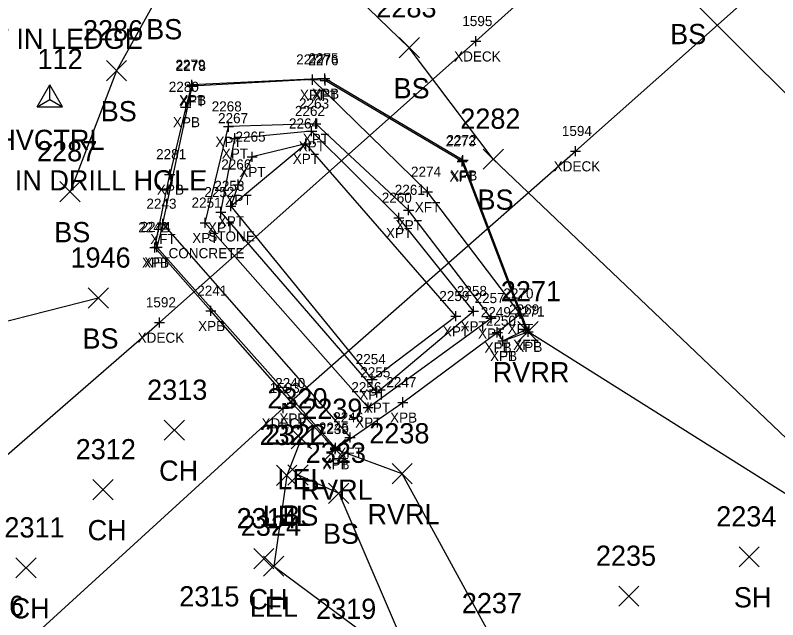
# Model space of a CAD drawing. Extents: x 1647133 to 1649138, y 411736 to 414924.
# Drawn here: x 1648877.6 to 1648953, y 412120.2 to 412180 of the extents above; entities that cross this region are included whole.
import ezdxf

# ---------------------------------------------------------------- set-up
doc = ezdxf.new("R2010")
doc.units = 0
for name, color, linetype in [('B_A', 7, 'Continuous'), ('B_C', 7, 'Continuous'), ('B_I', 7, 'Continuous'), ('B_TIC', 7, 'Continuous'), ('BELB', 7, 'Continuous'), ('BFT', 7, 'Continuous'), ('BSUBM', 7, 'Continuous'), ('C_A', 7, 'Continuous'), ('C_C', 7, 'Continuous'), ('C_I', 7, 'Continuous'), ('CPSM', 7, 'Continuous'), ('L_A', 7, 'Continuous'), ('L_I', 7, 'Continuous'), ('L_TIC', 7, 'Continuous'), ('LARO', 7, 'Continuous'), ('LAWE', 7, 'Continuous'), ('LELB', 7, 'Continuous')]:
    doc.layers.add(name, color=color, linetype=linetype)

msp = doc.modelspace()

# ---------------------------------------------------------------- linework, layer by layer
at = {"layer": 'B_TIC'}
for p, q in [((1648923.128, 412177.419), (1648923.203, 412177.419)), ((1648906.986, 412173.626), (1648907.061, 412173.626)), ((1648906.986, 412173.626), (1648907.061, 412173.626)), ((1648908.195, 412173.736), (1648908.27, 412173.736)), ((1648908.226, 412173.547), (1648908.302, 412173.547)), ((1648895.051, 412173.099), (1648895.126, 412173.099)), ((1648895.086, 412172.978), (1648895.162, 412172.978)), ((1648895.086, 412172.978), (1648895.162, 412172.978)), ((1648894.438, 412170.92), (1648894.513, 412170.92)), ((1648898.657, 412168.981), (1648898.733, 412168.981)), ((1648898.657, 412168.981), (1648898.733, 412168.981)), ((1648907.293, 412169.271), (1648907.368, 412169.271)), ((1648906.884, 412168.533), (1648906.96, 412168.533)), ((1648899.286, 412167.819), (1648899.362, 412167.819)), ((1648899.286, 412167.819), (1648899.362, 412167.819)), ((1648906.3, 412167.296), (1648906.376, 412167.296)), ((1648906.3, 412167.296), (1648906.376, 412167.296)), ((1648932.968, 412166.557), (1648933.043, 412166.557)), ((1648901.013, 412165.993), (1648901.089, 412165.993)), ((1648921.77, 412165.538), (1648921.845, 412165.538)), ((1648921.848, 412165.652), (1648921.923, 412165.652)), ((1648892.855, 412164.256), (1648892.931, 412164.256)), ((1648892.855, 412164.256), (1648892.931, 412164.256)), ((1648899.63, 412163.243), (1648899.706, 412163.243)), ((1648918.338, 412162.525), (1648918.413, 412162.525)), ((1648897.908, 412160.51), (1648897.983, 412160.51)), ((1648897.908, 412160.51), (1648897.983, 412160.51)), ((1648898.892, 412161.128), (1648898.968, 412161.128)), ((1648898.892, 412161.128), (1648898.968, 412161.128)), ((1648916.474, 412160.735), (1648916.55, 412160.735)), ((1648915.512, 412159.957), (1648915.588, 412159.957)), ((1648892.181, 412159.364), (1648892.257, 412159.364)), ((1648892.181, 412159.364), (1648892.257, 412159.364)), ((1648892.181, 412159.364), (1648892.257, 412159.364)), ((1648896.361, 412159.473), (1648896.437, 412159.473)), ((1648896.361, 412159.473), (1648896.437, 412159.473)), ((1648891.376, 412157.036), (1648891.451, 412157.036)), ((1648891.596, 412157.065), (1648891.672, 412157.065)), ((1648896.923, 412150.766), (1648896.998, 412150.766)), ((1648922.877, 412150.736), (1648922.952, 412150.736)), ((1648921.141, 412150.237), (1648921.217, 412150.237)), ((1648924.62, 412150.032), (1648924.695, 412150.032)), ((1648927.515, 412150.485), (1648927.59, 412150.485)), ((1648927.515, 412150.485), (1648927.59, 412150.485)), ((1648891.84, 412149.616), (1648891.916, 412149.616)), ((1648925.242, 412148.644), (1648925.318, 412148.644)), ((1648925.242, 412148.644), (1648925.318, 412148.644)), ((1648925.242, 412148.644), (1648925.318, 412148.644)), ((1648928.065, 412148.912), (1648928.14, 412148.912)), ((1648928.28, 412148.71), (1648928.355, 412148.71)), ((1648925.783, 412147.797), (1648925.858, 412147.797)), ((1648925.783, 412147.797), (1648925.858, 412147.797)), ((1648912.873, 412144.001), (1648912.948, 412144.001)), ((1648913.326, 412142.7), (1648913.401, 412142.7)), ((1648904.957, 412141.631), (1648905.033, 412141.631)), ((1648915.901, 412141.722), (1648915.976, 412141.722)), ((1648904.084, 412141.155), (1648904.16, 412141.155)), ((1648912.467, 412141.223), (1648912.543, 412141.223)), ((1648910.683, 412138.25), (1648910.758, 412138.25)), ((1648910.683, 412138.25), (1648910.758, 412138.25)), ((1648909.223, 412137.093), (1648909.299, 412137.093)), ((1648909.223, 412137.093), (1648909.299, 412137.093)), ((1648909.231, 412137.232), (1648909.307, 412137.232))]:
    msp.add_line(p, q, dxfattribs=at)
for points in [[(1648923.124, 412176.919), (1648923.124, 412177.919)], [(1648922.624, 412177.419), (1648923.624, 412177.419)], [(1648906.982, 412173.126), (1648906.982, 412174.126)], [(1648906.982, 412173.126), (1648906.982, 412174.126)], [(1648908.191, 412173.236), (1648908.191, 412174.236)], [(1648908.223, 412173.047), (1648908.223, 412174.047)], [(1648895.047, 412172.599), (1648895.047, 412173.599)], [(1648895.083, 412172.478), (1648895.083, 412173.478)], [(1648895.083, 412172.478), (1648895.083, 412173.478)], [(1648906.482, 412173.626), (1648907.482, 412173.626)], [(1648906.482, 412173.626), (1648907.482, 412173.626)], [(1648907.691, 412173.736), (1648908.691, 412173.736)], [(1648907.723, 412173.547), (1648908.723, 412173.547)], [(1648894.547, 412173.099), (1648895.547, 412173.099)], [(1648894.583, 412172.978), (1648895.583, 412172.978)], [(1648894.583, 412172.978), (1648895.583, 412172.978)], [(1648894.434, 412170.42), (1648894.434, 412171.42)], [(1648893.934, 412170.92), (1648894.934, 412170.92)], [(1648898.654, 412168.481), (1648898.654, 412169.481)], [(1648898.654, 412168.481), (1648898.654, 412169.481)], [(1648907.289, 412168.771), (1648907.289, 412169.771)], [(1648898.154, 412168.981), (1648899.154, 412168.981)], [(1648898.154, 412168.981), (1648899.154, 412168.981)], [(1648906.789, 412169.271), (1648907.789, 412169.271)], [(1648906.881, 412168.033), (1648906.881, 412169.033)], [(1648899.283, 412167.319), (1648899.283, 412168.319)], [(1648899.283, 412167.319), (1648899.283, 412168.319)], [(1648906.381, 412168.533), (1648907.381, 412168.533)], [(1648898.783, 412167.819), (1648899.783, 412167.819)], [(1648898.783, 412167.819), (1648899.783, 412167.819)], [(1648905.797, 412167.296), (1648906.797, 412167.296)], [(1648905.797, 412167.296), (1648906.797, 412167.296)], [(1648906.297, 412166.796), (1648906.297, 412167.796)], [(1648906.297, 412166.796), (1648906.297, 412167.796)], [(1648901.01, 412165.493), (1648901.01, 412166.493)], [(1648932.464, 412166.557), (1648933.464, 412166.557)], [(1648932.964, 412166.057), (1648932.964, 412167.057)], [(1648900.51, 412165.993), (1648901.51, 412165.993)], [(1648921.766, 412165.038), (1648921.766, 412166.038)], [(1648921.844, 412165.152), (1648921.844, 412166.152)], [(1648921.266, 412165.538), (1648922.266, 412165.538)], [(1648921.344, 412165.652), (1648922.344, 412165.652)], [(1648892.352, 412164.256), (1648893.352, 412164.256)], [(1648892.352, 412164.256), (1648893.352, 412164.256)], [(1648892.852, 412163.756), (1648892.852, 412164.756)], [(1648892.852, 412163.756), (1648892.852, 412164.756)], [(1648899.627, 412162.743), (1648899.627, 412163.743)], [(1648899.127, 412163.243), (1648900.127, 412163.243)], [(1648918.334, 412162.025), (1648918.334, 412163.025)], [(1648917.834, 412162.525), (1648918.834, 412162.525)], [(1648898.889, 412160.628), (1648898.889, 412161.628)], [(1648898.889, 412160.628), (1648898.889, 412161.628)], [(1648916.471, 412160.235), (1648916.471, 412161.235)], [(1648897.404, 412160.51), (1648898.404, 412160.51)], [(1648897.404, 412160.51), (1648898.404, 412160.51)], [(1648897.904, 412160.01), (1648897.904, 412161.01)], [(1648897.904, 412160.01), (1648897.904, 412161.01)], [(1648898.389, 412161.128), (1648899.389, 412161.128)], [(1648898.389, 412161.128), (1648899.389, 412161.128)], [(1648915.509, 412159.457), (1648915.509, 412160.457)], [(1648915.971, 412160.735), (1648916.971, 412160.735)], [(1648892.178, 412158.864), (1648892.178, 412159.864)], [(1648892.178, 412158.864), (1648892.178, 412159.864)], [(1648892.178, 412158.864), (1648892.178, 412159.864)], [(1648896.358, 412158.973), (1648896.358, 412159.973)], [(1648896.358, 412158.973), (1648896.358, 412159.973)], [(1648915.009, 412159.957), (1648916.009, 412159.957)], [(1648891.678, 412159.364), (1648892.678, 412159.364)], [(1648891.678, 412159.364), (1648892.678, 412159.364)], [(1648891.678, 412159.364), (1648892.678, 412159.364)], [(1648895.858, 412159.473), (1648896.858, 412159.473)], [(1648895.858, 412159.473), (1648896.858, 412159.473)], [(1648891.372, 412156.536), (1648891.372, 412157.536)], [(1648891.593, 412156.565), (1648891.593, 412157.565)], [(1648890.872, 412157.036), (1648891.872, 412157.036)], [(1648891.093, 412157.065), (1648892.093, 412157.065)], [(1648896.419, 412150.766), (1648897.419, 412150.766)], [(1648896.919, 412150.266), (1648896.919, 412151.266)], [(1648921.138, 412149.737), (1648921.138, 412150.737)], [(1648922.373, 412150.736), (1648923.373, 412150.736)], [(1648922.873, 412150.236), (1648922.873, 412151.236)], [(1648927.511, 412149.985), (1648927.511, 412150.985)], [(1648927.511, 412149.985), (1648927.511, 412150.985)], [(1648891.837, 412149.116), (1648891.837, 412150.116)], [(1648920.638, 412150.237), (1648921.638, 412150.237)], [(1648924.116, 412150.032), (1648925.116, 412150.032)], [(1648924.616, 412149.532), (1648924.616, 412150.532)], [(1648927.011, 412150.485), (1648928.011, 412150.485)], [(1648927.011, 412150.485), (1648928.011, 412150.485)], [(1648891.337, 412149.616), (1648892.337, 412149.616)], [(1648925.239, 412148.144), (1648925.239, 412149.144)], [(1648925.239, 412148.144), (1648925.239, 412149.144)], [(1648925.239, 412148.144), (1648925.239, 412149.144)], [(1648928.061, 412148.412), (1648928.061, 412149.412)], [(1648928.276, 412148.21), (1648928.276, 412149.21)], [(1648924.739, 412148.644), (1648925.739, 412148.644)], [(1648924.739, 412148.644), (1648925.739, 412148.644)], [(1648924.739, 412148.644), (1648925.739, 412148.644)], [(1648927.561, 412148.912), (1648928.561, 412148.912)], [(1648927.776, 412148.71), (1648928.776, 412148.71)], [(1648925.279, 412147.797), (1648926.279, 412147.797)], [(1648925.279, 412147.797), (1648926.279, 412147.797)], [(1648925.779, 412147.296), (1648925.779, 412148.297)], [(1648925.779, 412147.296), (1648925.779, 412148.297)], [(1648912.369, 412144.001), (1648913.369, 412144.001)], [(1648912.869, 412143.501), (1648912.869, 412144.501)], [(1648913.322, 412142.2), (1648913.322, 412143.2)], [(1648912.822, 412142.7), (1648913.822, 412142.7)], [(1648904.081, 412140.655), (1648904.081, 412141.655)], [(1648904.454, 412141.631), (1648905.454, 412141.631)], [(1648904.954, 412141.131), (1648904.954, 412142.131)], [(1648912.464, 412140.723), (1648912.464, 412141.723)], [(1648915.397, 412141.722), (1648916.397, 412141.722)], [(1648915.897, 412141.222), (1648915.897, 412142.222)], [(1648903.581, 412141.155), (1648904.581, 412141.155)], [(1648911.964, 412141.223), (1648912.964, 412141.223)], [(1648910.68, 412137.75), (1648910.68, 412138.75)], [(1648910.68, 412137.75), (1648910.68, 412138.75)], [(1648910.18, 412138.25), (1648911.18, 412138.25)], [(1648910.18, 412138.25), (1648911.18, 412138.25)], [(1648908.72, 412137.093), (1648909.72, 412137.093)], [(1648908.72, 412137.093), (1648909.72, 412137.093)], [(1648908.728, 412137.232), (1648909.728, 412137.232)], [(1648909.22, 412136.593), (1648909.22, 412137.593)], [(1648909.22, 412136.593), (1648909.22, 412137.593)], [(1648909.228, 412136.732), (1648909.228, 412137.732)]]:
    msp.add_lwpolyline(points, dxfattribs=at)
at = {"layer": 'BELB'}
for points in [[(1648856.366, 412097.638), (1648845.782, 412109.602), (1648891.837, 412149.616), (1648923.124, 412177.419), (1648960.58, 412211.026), (1648974.892, 412224.907)], [(1648856.366, 412097.638), (1648904.081, 412141.155), (1648932.964, 412166.557), (1648970.055, 412199.522), (1648985.33, 412212.818), (1648974.892, 412224.907)]]:
    msp.add_lwpolyline(points, dxfattribs=at)
at = {"layer": 'BFT'}
for points in [[(1648925.239, 412148.644), (1648925.779, 412147.797), (1648928.061, 412148.912), (1648927.511, 412150.485), (1648921.766, 412165.538), (1648908.223, 412173.547), (1648906.982, 412173.626), (1648895.083, 412172.978)], [(1648925.239, 412148.644), (1648927.511, 412150.485), (1648918.334, 412162.525), (1648906.982, 412173.626)], [(1648892.178, 412159.364), (1648895.083, 412172.978)], [(1648892.178, 412159.364), (1648891.593, 412157.065), (1648909.228, 412137.232), (1648910.68, 412138.25)], [(1648892.178, 412159.364), (1648910.68, 412138.25)]]:
    msp.add_lwpolyline(points, dxfattribs=at)
at = {"layer": 'BSUBM'}
for points in [[(1648925.779, 412147.797), (1648928.276, 412148.71), (1648921.844, 412165.652), (1648908.191, 412173.736), (1648895.047, 412173.099), (1648894.434, 412170.92), (1648892.852, 412164.256)], [(1648896.358, 412159.473), (1648912.464, 412141.223), (1648924.616, 412150.032), (1648916.471, 412160.735), (1648907.289, 412169.271), (1648898.654, 412168.981)], [(1648896.358, 412159.473), (1648898.654, 412168.981)], [(1648897.904, 412160.51), (1648913.322, 412142.7), (1648922.873, 412150.736), (1648915.509, 412159.957), (1648906.881, 412168.533), (1648899.283, 412167.819)], [(1648897.904, 412160.51), (1648899.283, 412167.819)], [(1648898.889, 412161.128), (1648906.297, 412167.296)], [(1648898.889, 412161.128), (1648912.869, 412144.001), (1648921.138, 412150.237), (1648906.297, 412167.296), (1648901.01, 412165.993), (1648899.627, 412163.243)], [(1648909.22, 412137.093), (1648904.954, 412141.631), (1648896.919, 412150.766), (1648891.372, 412157.036), (1648892.852, 412164.256)], [(1648899.627, 412163.243), (1648898.889, 412161.128)], [(1648909.22, 412137.093), (1648915.897, 412141.722), (1648925.239, 412148.644)]]:
    msp.add_lwpolyline(points, dxfattribs=at)
at = {"layer": 'CPSM'}
for p, q in [((1648879.764, 412170.95), (1648881.014, 412173.115)), ((1648882.264, 412170.95), (1648881.014, 412173.115)), ((1648881.014, 412171.671), (1648881.014, 412173.115)), ((1648879.764, 412170.95), (1648881.014, 412171.671)), ((1648881.014, 412171.671), (1648881.014, 412171.671)), ((1648881.014, 412171.671), (1648882.264, 412170.95)), ((1648879.764, 412170.95), (1648882.264, 412170.95))]:
    msp.add_line(p, q, dxfattribs=at)
at = {"layer": 'L_TIC'}
for points in [[(1648915.538, 412175.778), (1648917.538, 412177.778)], [(1648917.538, 412175.778), (1648915.538, 412177.778)], [(1648886.588, 412173.507), (1648888.588, 412175.507)], [(1648888.588, 412173.507), (1648886.588, 412175.507)], [(1648923.838, 412164.768), (1648925.838, 412166.768)], [(1648925.838, 412164.768), (1648923.838, 412166.768)], [(1648881.995, 412161.551), (1648883.995, 412163.551)], [(1648883.995, 412161.551), (1648881.995, 412163.551)], [(1648884.787, 412151.041), (1648886.787, 412153.041)], [(1648886.787, 412151.041), (1648884.787, 412153.041)], [(1648927.276, 412147.71), (1648929.276, 412149.71)], [(1648929.276, 412147.71), (1648927.276, 412149.71)], [(1648892.313, 412137.973), (1648894.313, 412139.973)], [(1648894.313, 412137.973), (1648892.313, 412139.973)], [(1648904.854, 412137.123), (1648906.854, 412139.123)], [(1648906.854, 412137.123), (1648904.854, 412139.123)], [(1648908.22, 412136.093), (1648910.22, 412138.093)], [(1648910.22, 412136.093), (1648908.22, 412138.093)], [(1648904.543, 412133.547), (1648906.543, 412135.547)], [(1648906.543, 412133.547), (1648904.543, 412135.547)], [(1648914.837, 412133.668), (1648916.837, 412135.668)], [(1648916.837, 412133.668), (1648914.837, 412135.668)], [(1648903.419, 412133.508), (1648905.419, 412135.508)], [(1648905.419, 412133.508), (1648903.419, 412135.508)], [(1648885.248, 412132.095), (1648887.248, 412134.095)], [(1648887.248, 412132.095), (1648885.248, 412134.095)], [(1648908.562, 412131.742), (1648910.562, 412133.742)], [(1648910.562, 412131.742), (1648908.562, 412133.742)], [(1648901.154, 412125.274), (1648903.154, 412127.274)], [(1648903.154, 412125.274), (1648901.154, 412127.274)], [(1648949.135, 412125.455), (1648951.135, 412127.455)], [(1648951.135, 412125.455), (1648949.135, 412127.455)], [(1648902.138, 412124.533), (1648904.138, 412126.533)], [(1648904.138, 412124.533), (1648902.138, 412126.533)], [(1648877.635, 412124.367), (1648879.635, 412126.367)], [(1648879.635, 412124.367), (1648877.635, 412126.367)], [(1648937.243, 412121.57), (1648939.243, 412123.57)], [(1648939.243, 412121.57), (1648937.243, 412123.57)]]:
    msp.add_lwpolyline(points, dxfattribs=at)
at = {"layer": 'LARO'}
msp.add_lwpolyline([(1648905.854, 412138.123), (1648904.419, 412134.508), (1648903.138, 412125.533), (1648917.111, 412115.154)], dxfattribs=at)
at = {"layer": 'LAWE'}
for points in [[(1648975.479, 412083.808), (1648974.711, 412106.249), (1648959.743, 412128.88), (1648928.276, 412148.71)], [(1648975.479, 412083.808), (1648956.323, 412088.342), (1648932.321, 412103.746), (1648924.989, 412117.882), (1648915.837, 412134.668), (1648909.22, 412137.093)]]:
    msp.add_lwpolyline(points, dxfattribs=at)
at = {"layer": 'LELB'}
for points in [[(1648988.623, 412076.26), (1648991.76, 412087.718), (1648981.689, 412120.13), (1648975.99, 412150.035), (1648943.88, 412182.13), (1648927.941, 412194.053), (1648916.818, 412208.897), (1648904.261, 412218.436), (1648897.394, 412214.008), (1648892.18, 412224.475), (1648890.028, 412246.184), (1648887.988, 412265.678), (1648880.678, 412274.106), (1648875.374, 412283.752)], [(1648974.711, 412106.249), (1648962.143, 412130.242), (1648924.838, 412165.768), (1648916.538, 412176.778), (1648904.426, 412188.506), (1648892.086, 412182.611), (1648887.588, 412174.507), (1648882.995, 412162.551)], [(1648885.787, 412152.041), (1648870.49, 412148.148)], [(1648905.543, 412134.547), (1648909.562, 412132.742), (1648917.111, 412115.154), (1648917.834, 412101.461), (1648934.194, 412092.008), (1648947.536, 412086.809), (1648962.617, 412077.56), (1648983.8, 412066.358)]]:
    msp.add_lwpolyline(points, dxfattribs=at)

# ---------------------------------------------------------------- texts
at = {"layer": 'B_A'}
for s, p in [('XDECK', (1648920.967, 412175.419)), ('XFT', (1648905.726, 412171.626)), ('XFT', (1648905.726, 412171.626)), ('XPB', (1648906.927, 412171.736)), ('XFT', (1648906.967, 412171.547)), ('XPB', (1648893.783, 412171.099)), ('XFT', (1648893.827, 412170.978)), ('XFT', (1648893.827, 412170.978)), ('XPB', (1648893.17, 412168.92)), ('XPT', (1648897.374, 412166.981)), ('XPT', (1648897.374, 412166.981)), ('XPT', (1648906.01, 412167.271)), ('XPT', (1648905.601, 412166.533)), ('XPT', (1648898.003, 412165.819)), ('XPT', (1648898.003, 412165.819)), ('XPT', (1648905.017, 412165.296)), ('XPT', (1648905.017, 412165.296)), ('XPT', (1648899.73, 412163.993)), ('XDECK', (1648930.807, 412164.557)), ('XFT', (1648920.51, 412163.538)), ('XPB', (1648920.581, 412163.652)), ('XPB', (1648891.588, 412162.256)), ('XPB', (1648891.588, 412162.256)), ('XPT', (1648898.347, 412161.243)), ('XFT', (1648917.078, 412160.525)), ('XPT', (1648897.609, 412159.128)), ('XPT', (1648897.609, 412159.128)), ('XPT', (1648915.191, 412158.735)), ('XPT', (1648896.625, 412158.51)), ('XPT', (1648896.625, 412158.51)), ('XPT', (1648914.229, 412157.957)), ('XFT', (1648890.922, 412157.364)), ('XFT', (1648890.922, 412157.364)), ('XFT', (1648890.922, 412157.364)), ('XPT', (1648895.078, 412157.473)), ('XPT', (1648895.078, 412157.473)), ('XPB', (1648890.109, 412155.036)), ('XFT', (1648890.337, 412155.065)), ('XPB', (1648895.656, 412148.766)), ('XPT', (1648919.858, 412148.237)), ('XPT', (1648921.594, 412148.736)), ('XFT', (1648926.256, 412148.485)), ('XFT', (1648926.256, 412148.485)), ('XDECK', (1648889.679, 412147.616)), ('XPT', (1648923.337, 412148.032)), ('XPB', (1648923.975, 412146.644)), ('XFT', (1648923.983, 412146.644)), ('XFT', (1648923.983, 412146.644)), ('XFT', (1648926.806, 412146.912)), ('XPB', (1648927.012, 412146.71)), ('XPB', (1648924.515, 412145.797)), ('XFT', (1648924.523, 412145.797)), ('XPT', (1648911.59, 412142.001)), ('XPT', (1648912.043, 412140.7)), ('XDECK', (1648901.923, 412139.155)), ('XPB', (1648903.69, 412139.631)), ('XPT', (1648911.184, 412139.223)), ('XPB', (1648914.634, 412139.722)), ('XFT', (1648909.424, 412136.25)), ('XFT', (1648909.424, 412136.25)), ('XPB', (1648907.956, 412135.093)), ('XPB', (1648907.956, 412135.093)), ('XFT', (1648907.972, 412135.232))]:
    msp.add_text(s, height=1, dxfattribs=at).set_placement(p)
at = {"layer": 'B_C'}
for s, p in [('STONE', (1648896.66, 412157.628)), ('STONE', (1648896.66, 412157.628)), ('CONCRETE', (1648892.736, 412155.973)), ('CONCRETE', (1648892.736, 412155.973))]:
    msp.add_text(s, height=1, dxfattribs=at).set_placement(p)
at = {"layer": 'B_I'}
for s, p in [('1595', (1648921.778, 412178.919)), ('2275', (1648906.561, 412175.236)), ('2279', (1648893.413, 412174.599)), ('2277', (1648905.352, 412175.126)), ('2277', (1648905.352, 412175.126)), ('2276', (1648906.566, 412175.047)), ('2278', (1648893.453, 412174.478)), ('2278', (1648893.453, 412174.478)), ('2280', (1648892.761, 412172.42)), ('2263', (1648905.636, 412170.771)), ('2268', (1648897, 412170.481)), ('2268', (1648897, 412170.481)), ('2262', (1648905.227, 412170.033)), ('2267', (1648897.629, 412169.319)), ('2267', (1648897.629, 412169.319)), ('2264', (1648904.643, 412168.796)), ('2264', (1648904.643, 412168.796)), ('1594', (1648931.618, 412168.057)), ('2265', (1648899.356, 412167.493)), ('2273', (1648920.136, 412167.038)), ('2272', (1648920.214, 412167.152)), ('2281', (1648891.505, 412165.756)), ('2281', (1648891.505, 412165.756)), ('2266', (1648897.946, 412164.743)), ('2274', (1648916.704, 412164.025)), ('2253', (1648897.259, 412162.628)), ('2253', (1648897.259, 412162.628)), ('2252', (1648896.274, 412162.01)), ('2252', (1648896.274, 412162.01)), ('2261', (1648915.101, 412162.235)), ('2251', (1648895.011, 412160.973)), ('2251', (1648895.011, 412160.973)), ('2260', (1648913.812, 412161.457)), ('2243', (1648890.548, 412160.864)), ('2243', (1648890.548, 412160.864)), ('2243', (1648890.548, 412160.864)), ('2242', (1648889.742, 412158.536)), ('2244', (1648889.963, 412158.565)), ('2241', (1648895.573, 412152.266)), ('2258', (1648921.243, 412152.236)), ('2270', (1648925.838, 412151.985)), ('2270', (1648925.838, 412151.985)), ('1592', (1648890.49, 412151.116)), ('2259', (1648919.504, 412151.737)), ('2257', (1648922.986, 412151.532)), ('2269', (1648926.404, 412150.412)), ('2249', (1648923.605, 412150.144)), ('2249', (1648923.605, 412150.144)), ('2249', (1648923.605, 412150.144)), ('2271', (1648926.93, 412150.21)), ('2250', (1648924.106, 412149.297)), ('2250', (1648924.106, 412149.297)), ('2254', (1648911.239, 412145.501)), ('2255', (1648911.692, 412144.2)), ('2240', (1648903.28, 412143.131)), ('2247', (1648914.268, 412143.222)), ('1593', (1648902.734, 412142.655)), ('2256', (1648910.806, 412142.723)), ('2246', (1648909.022, 412139.75)), ('2246', (1648909.022, 412139.75)), ('2239', (1648907.586, 412138.593)), ('2239', (1648907.586, 412138.593)), ('2245', (1648907.598, 412138.732))]:
    msp.add_text(s, height=1, dxfattribs=at).set_placement(p)
at = {"layer": 'C_A'}
msp.add_text('HVCTRL', height=2, dxfattribs=at).set_placement((1648875.707, 412166.671))
at = {"layer": 'C_C'}
for s, p in [('DISK SET IN LEDGE', (1648864.765, 412176.668)), ('HUB W/TACK IN DRILL HOLE', (1648860.006, 412162.671))]:
    msp.add_text(s, height=2, dxfattribs=at).set_placement(p)
at = {"layer": 'C_I'}
msp.add_text('112', height=2, dxfattribs=at).set_placement((1648879.786, 412174.671))
at = {"layer": 'L_A'}
for s, p in [('BS', (1648890.527, 412177.611)), ('BS', (1648942.321, 412177.13)), ('BS', (1648914.979, 412171.778)), ('BS', (1648886.029, 412169.507)), ('BS', (1648923.279, 412160.768)), ('BS', (1648881.436, 412157.551)), ('BS', (1648884.228, 412147.041)), ('RVRR', (1648924.788, 412143.71)), ('CH', (1648891.801, 412133.973)), ('LEL', (1648903.492, 412133.123)), ('RVRL', (1648905.787, 412132.093)), ('LEL', (1648902.056, 412129.508)), ('BS', (1648903.984, 412129.547)), ('RVRL', (1648912.404, 412129.668)), ('CH', (1648884.736, 412128.095)), ('BS', (1648908.003, 412127.742)), ('SH', (1648948.623, 412121.455)), ('CH', (1648900.642, 412121.274)), ('CH', (1648877.123, 412120.367)), ('LEL', (1648900.776, 412120.533))]:
    msp.add_text(s, height=2, dxfattribs=at).set_placement(p)
at = {"layer": 'L_I'}
for s, p in [('2283', (1648913.278, 412179.778)), ('2286', (1648884.273, 412177.507)), ('2282', (1648921.578, 412168.768)), ('2287', (1648879.735, 412165.551)), ('1946', (1648883.039, 412155.041)), ('2271', (1648925.583, 412151.71)), ('2313', (1648890.62, 412141.973)), ('2320', (1648902.508, 412141.123)), ('2239', (1648905.952, 412140.093)), ('2321', (1648901.726, 412137.508)), ('2322', (1648902.284, 412137.547)), ('2238', (1648912.577, 412137.668)), ('2312', (1648883.555, 412136.095)), ('2323', (1648906.302, 412135.742)), ('2314', (1648899.461, 412129.274)), ('2234', (1648946.875, 412129.455)), ('2311', (1648876.509, 412128.367)), ('2324', (1648899.878, 412128.533)), ('2235', (1648934.983, 412125.57)), ('2315', (1648893.792, 412121.552)), ('2237', (1648921.729, 412120.882)), ('1966', (1648872.515, 412120.612)), ('2319', (1648907.319, 412120.316))]:
    msp.add_text(s, height=2, dxfattribs=at).set_placement(p)

doc.saveas('drawing.dxf')
